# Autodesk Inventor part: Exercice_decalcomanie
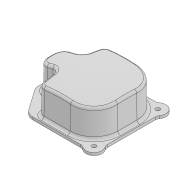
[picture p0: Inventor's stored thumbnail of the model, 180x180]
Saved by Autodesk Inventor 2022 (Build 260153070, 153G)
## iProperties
Created: 2019-12
Part Number: Exercice_decalcomanie
Material: Générique
Document SubType Name: Modeling
Designer: Fabian
Density: 1 g/cm^3
Appearance: Par défaut
Author: Fabian
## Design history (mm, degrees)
sketch "Esquisse1"
  geometry: L1 (0, 70)-(0, -66.117); L2 (90, 0)-(-70, 0); L3 (90, 14.325)-(90, 0); L4 (-70, 45)-(-70, 0); L5 (44.578, 70)-(-45, 70); L6 (86.745, 24.649)-(60.961, 61.472); L7 (83, 0)-(83, 5); L8 (65, 23)-(55, 23); L9 (43, 35)-(43, 51); L10 (31, 63)-(-18, 63); L11 (-63, 18)-(-63, 0); L12 (-63, -18)-(-63, 0); L13 (0, -70)-(0, 66.117); L14 (-70, -45)-(-70, 0); L15 (31, -63)-(-18, -63); L16 (44.578, -70)-(-45, -70); L17 (43, -35)-(43, -51); L18 (90, -14.325)-(90, 0); L19 (86.745, -24.649)-(60.961, -61.472); L20 (83, 0)-(83, -5); L21 (65, -23)-(55, -23); C1 r 4 at (-60, 60); C2 r 6 at (55, 35); C3 r 4 at (-60, -60); C4 r 6 at (55, -35); A1 r 15 centre (-60, 60) between (-51, 72) and (-72, 51); A2 r 12 centre (55, 35) between (43, 35) and (55, 23); A3 r 12 centre (31, 51) between (43, 51) and (31, 63); A4 r 18 centre (72, 14.325) between (90, 14.325) and (86.745, 24.649); A5 r 20 centre (44.578, 50) between (60.961, 61.472) and (44.578, 70); A6 r 10 centre (-45, 80) between (-51, 72) and (-45, 70); A7 r 10 centre (-80, 45) between (-70, 45) and (-72, 51); A8 r 18 centre (65, 5) between (83, 5) and (65, 23); A9 r 45 centre (-18, 18) between (-18, 63) and (-63, 18); A10 r 45 centre (-18, -18) between (-63, -18) and (-18, -63); A11 r 12 centre (31, -51) between (31, -63) and (43, -51); A12 r 10 centre (-45, -80) between (-45, -70) and (-51, -72); A13 r 15 centre (-60, -60) between (-72, -51) and (-51, -72); A14 r 10 centre (-80, -45) between (-72, -51) and (-70, -45); A15 r 12 centre (55, -35) between (55, -23) and (43, -35); A16 r 20 centre (44.578, -50) between (44.578, -70) and (60.961, -61.472); A17 r 18 centre (65, -5) between (65, -23) and (83, -5); A18 r 18 centre (72, -14.325) between (86.745, -24.649) and (90, -14.325); 7 further points
  constraints: 44 end point, 40 point on circle, 32 symmetric about line, 22 centre point, 16 tangent, 14 point on line, 5 perpendicular, 4 coincident, 3 vertical, 2 horizontal, 11 other
  dimensions: "d2" = 70 distance between parallel lines of L4 L1; "d3" = 90 distance between parallel lines of L3 L1; "d5" = 30 diameter of A1; "d6" = 140 diameter of L5 L2; "d7" = 20 distance of point (90, 20) L2.start; "d8" = 35 deg angle of L3 L6; "d9" = 120 diameter of A1.centre L2; "d11" = 60 distance from line of A1.centre L1; "d12" = 8 diameter of C1; "d13" = 70 diameter of C2.centre L2; "d14" = 55 distance from line of C2.centre L1; "d15" = 12 diameter of C2; "d16" = 83 distance between parallel lines of L7 L1; "d17" = 63 distance between parallel lines of L11 L1; "d18" = 46 diameter of L8 L2 (derived); "d19" = 126 diameter of L10 L2; "d21" = 12 radius of A2; "d22" = 43 distance between parallel lines of L9 L1 (derived); "d23" = 12 radius of A3 (derived); "d24" = 18 radius of A4 (derived); "d25" = 20 radius of A5; "d26" = 10 radius of A6; "d27" = 10 radius of A7; "d28" = 18 radius of A8; "d29" = 45 radius of A9
extrude "Extrusion1" new body sketch "Esquisse1" distance "d30" = 65; taper "d31" = -1 deg
sketch "Esquisse2"
  geometry: L1 (-81.865, 65)-(61.865, 65); L2 (0, -455)-(0, 65); L3 (18, 65)-(-31, 65) reference; L4 (-55, 65)-(-65, 65) reference; A1 r 260 centre (0, -195) between (0, -455) and (0, 65); 1 further point
  constraints: 4 end point, 2 point on circle, 1 centre point, 1 collinear, 1 point on line, 1 tangent, 1 vertical, 1 vertical alignment
  dimensions: "d32" = 520 diameter of A1
revolve "Révolution1" sketch "Esquisse2" stored, may be unused: angle "d33" = 90 deg
fillet "Congé1" dims "d36" = 5
feature "Coque1" dims "d37" = 3
extrude "Extrusion2" join sketch "Esquisse1" distance "d34" = 5; taper "d35" = 0 deg
fillet "Congé2" dims "d38" = 5
node "Solide1"
